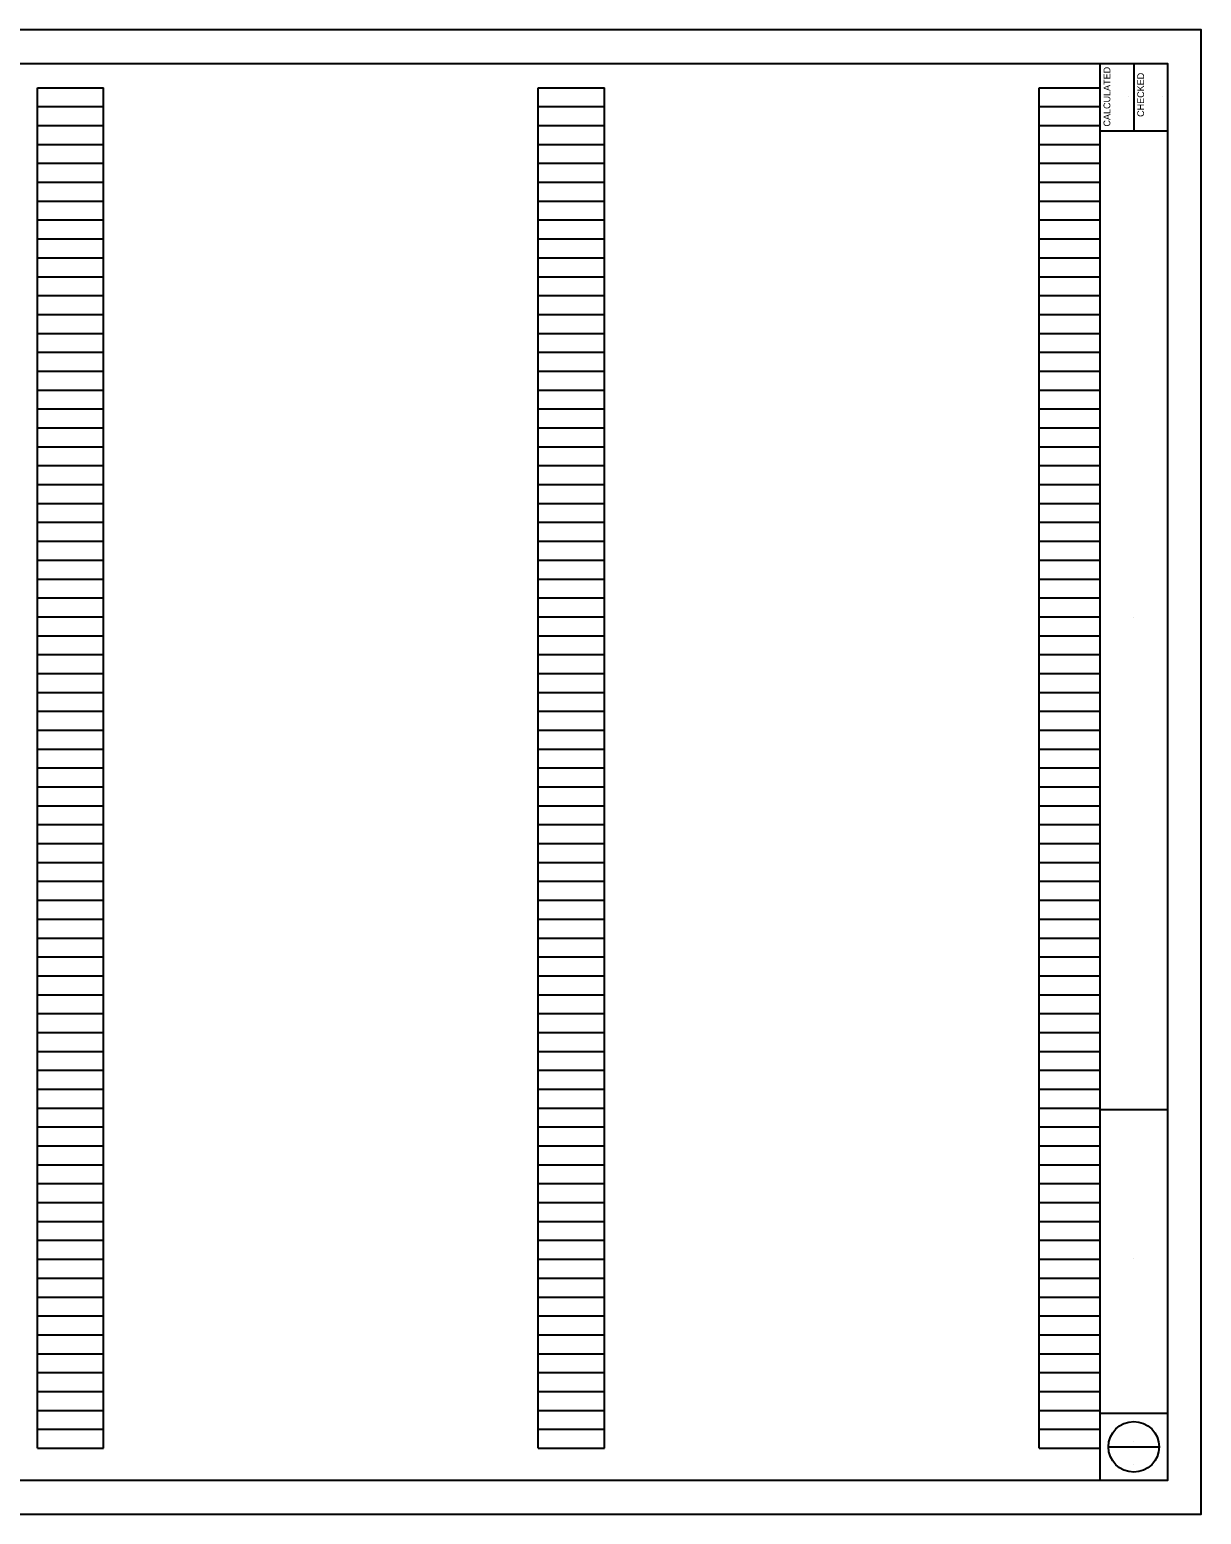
# Model space of a CAD drawing. Extents: x 0 to 34, y 0 to 22.
# Drawn here: x 16.65 to 34, y 0 to 22 of the extents above; entities that cross this region are included whole.
import ezdxf

# ---------------------------------------------------------------- set-up
doc = ezdxf.new("R2010")
doc.units = 0
for name, color, linetype in [('SH_Border', 7, 'Continuous'), ('SH_Cut_Line', 7, 'Continuous'), ('SH_Data', 7, 'Continuous')]:
    doc.layers.add(name, color=color, linetype=linetype)

msp = doc.modelspace()

# ---------------------------------------------------------------- linework, layer by layer
at = {"layer": 'SH_Border'}
for p, q in [((32.5, 0.5), (32.5, 21.5)), ((33, 21.5), (33, 20.5)), ((32.5, 20.5), (33.5, 20.5)), ((32.5, 6), (33.5, 6)), ((32.5, 1.5), (33.5, 1.5))]:
    msp.add_line(p, q, dxfattribs=at)
msp.add_lwpolyline([(2, 21.5), (33.5, 21.5), (33.5, 0.5), (2, 0.5)], close=True, dxfattribs=at)
at = {"layer": 'SH_Cut_Line'}
msp.add_lwpolyline([(0, 0), (34, 0), (34, 22), (0, 22)], close=True, dxfattribs=at)
at = {"layer": 'SH_Data'}
for p, q in [((16.76, 0.98), (16.76, 21.14)), ((16.76, 21.14), (17.74, 21.14)), ((17.74, 0.98), (17.74, 21.14)), ((24.18, 0.98), (24.18, 21.14)), ((24.18, 21.14), (25.16, 21.14)), ((25.16, 0.98), (25.16, 21.14)), ((31.6, 0.98), (31.6, 21.14)), ((31.6, 21.14), (32.5, 21.14)), ((32.5, 0.98), (32.5, 21.14)), ((32.92, 21.004), (32.92, 21.004)), ((33.42, 21.004), (33.42, 21.004)), ((16.76, 20.86), (17.74, 20.86)), ((24.18, 20.86), (25.16, 20.86)), ((31.6, 20.86), (32.5, 20.86)), ((16.76, 20.58), (17.74, 20.58)), ((24.18, 20.58), (25.16, 20.58)), ((31.6, 20.58), (32.5, 20.58)), ((16.76, 20.3), (17.74, 20.3)), ((24.18, 20.3), (25.16, 20.3)), ((31.6, 20.3), (32.5, 20.3)), ((16.76, 20.02), (17.74, 20.02)), ((24.18, 20.02), (25.16, 20.02)), ((31.6, 20.02), (32.5, 20.02)), ((16.76, 19.74), (17.74, 19.74)), ((24.18, 19.74), (25.16, 19.74)), ((31.6, 19.74), (32.5, 19.74)), ((16.76, 19.46), (17.74, 19.46)), ((24.18, 19.46), (25.16, 19.46)), ((31.6, 19.46), (32.5, 19.46)), ((16.76, 19.18), (17.74, 19.18)), ((24.18, 19.18), (25.16, 19.18)), ((31.6, 19.18), (32.5, 19.18)), ((16.76, 18.9), (17.74, 18.9)), ((24.18, 18.9), (25.16, 18.9)), ((31.6, 18.9), (32.5, 18.9)), ((16.76, 18.62), (17.74, 18.62)), ((24.18, 18.62), (25.16, 18.62)), ((31.6, 18.62), (32.5, 18.62)), ((16.76, 18.34), (17.74, 18.34)), ((24.18, 18.34), (25.16, 18.34)), ((31.6, 18.34), (32.5, 18.34)), ((16.76, 18.06), (17.74, 18.06)), ((24.18, 18.06), (25.16, 18.06)), ((31.6, 18.06), (32.5, 18.06)), ((16.76, 17.78), (17.74, 17.78)), ((24.18, 17.78), (25.16, 17.78)), ((31.6, 17.78), (32.5, 17.78)), ((16.76, 17.5), (17.74, 17.5)), ((24.18, 17.5), (25.16, 17.5)), ((31.6, 17.5), (32.5, 17.5)), ((16.76, 17.22), (17.74, 17.22)), ((24.18, 17.22), (25.16, 17.22)), ((31.6, 17.22), (32.5, 17.22)), ((16.76, 16.94), (17.74, 16.94)), ((24.18, 16.94), (25.16, 16.94)), ((31.6, 16.94), (32.5, 16.94)), ((16.76, 16.66), (17.74, 16.66)), ((24.18, 16.66), (25.16, 16.66)), ((31.6, 16.66), (32.5, 16.66)), ((16.76, 16.38), (17.74, 16.38)), ((24.18, 16.38), (25.16, 16.38)), ((31.6, 16.38), (32.5, 16.38)), ((16.76, 16.1), (17.74, 16.1)), ((24.18, 16.1), (25.16, 16.1)), ((31.6, 16.1), (32.5, 16.1)), ((16.76, 15.82), (17.74, 15.82)), ((24.18, 15.82), (25.16, 15.82)), ((31.6, 15.82), (32.5, 15.82)), ((16.76, 15.54), (17.74, 15.54)), ((24.18, 15.54), (25.16, 15.54)), ((31.6, 15.54), (32.5, 15.54)), ((16.76, 15.26), (17.74, 15.26)), ((24.18, 15.26), (25.16, 15.26)), ((31.6, 15.26), (32.5, 15.26)), ((16.76, 14.98), (17.74, 14.98)), ((24.18, 14.98), (25.16, 14.98)), ((31.6, 14.98), (32.5, 14.98)), ((16.76, 14.7), (17.74, 14.7)), ((24.18, 14.7), (25.16, 14.7)), ((31.6, 14.7), (32.5, 14.7)), ((16.76, 14.42), (17.74, 14.42)), ((24.18, 14.42), (25.16, 14.42)), ((31.6, 14.42), (32.5, 14.42)), ((16.76, 14.14), (17.74, 14.14)), ((24.18, 14.14), (25.16, 14.14)), ((31.6, 14.14), (32.5, 14.14)), ((16.76, 13.86), (17.74, 13.86)), ((24.18, 13.86), (25.16, 13.86)), ((31.6, 13.86), (32.5, 13.86)), ((16.76, 13.58), (17.74, 13.58)), ((24.18, 13.58), (25.16, 13.58)), ((31.6, 13.58), (32.5, 13.58)), ((16.76, 13.3), (17.74, 13.3)), ((24.18, 13.3), (25.16, 13.3)), ((31.6, 13.3), (32.5, 13.3)), ((33, 13.292), (33, 13.292)), ((16.76, 13.02), (17.74, 13.02)), ((24.18, 13.02), (25.16, 13.02)), ((31.6, 13.02), (32.5, 13.02)), ((16.76, 12.74), (17.74, 12.74)), ((24.18, 12.74), (25.16, 12.74)), ((31.6, 12.74), (32.5, 12.74)), ((16.76, 12.46), (17.74, 12.46)), ((24.18, 12.46), (25.16, 12.46)), ((31.6, 12.46), (32.5, 12.46)), ((16.76, 12.18), (17.74, 12.18)), ((24.18, 12.18), (25.16, 12.18)), ((31.6, 12.18), (32.5, 12.18)), ((16.76, 11.9), (17.74, 11.9)), ((24.18, 11.9), (25.16, 11.9)), ((31.6, 11.9), (32.5, 11.9)), ((16.76, 11.62), (17.74, 11.62)), ((24.18, 11.62), (25.16, 11.62)), ((31.6, 11.62), (32.5, 11.62)), ((16.76, 11.34), (17.74, 11.34)), ((24.18, 11.34), (25.16, 11.34)), ((31.6, 11.34), (32.5, 11.34)), ((16.76, 11.06), (17.74, 11.06)), ((24.18, 11.06), (25.16, 11.06)), ((31.6, 11.06), (32.5, 11.06)), ((16.76, 10.78), (17.74, 10.78)), ((24.18, 10.78), (25.16, 10.78)), ((31.6, 10.78), (32.5, 10.78)), ((16.76, 10.5), (17.74, 10.5)), ((24.18, 10.5), (25.16, 10.5)), ((31.6, 10.5), (32.5, 10.5)), ((16.76, 10.22), (17.74, 10.22)), ((24.18, 10.22), (25.16, 10.22)), ((31.6, 10.22), (32.5, 10.22)), ((16.76, 9.94), (17.74, 9.94)), ((24.18, 9.94), (25.16, 9.94)), ((31.6, 9.94), (32.5, 9.94)), ((16.76, 9.66), (17.74, 9.66)), ((24.18, 9.66), (25.16, 9.66)), ((31.6, 9.66), (32.5, 9.66)), ((16.76, 9.38), (17.74, 9.38)), ((24.18, 9.38), (25.16, 9.38)), ((31.6, 9.38), (32.5, 9.38)), ((16.76, 9.1), (17.74, 9.1)), ((24.18, 9.1), (25.16, 9.1)), ((31.6, 9.1), (32.5, 9.1)), ((16.76, 8.82), (17.74, 8.82)), ((24.18, 8.82), (25.16, 8.82)), ((31.6, 8.82), (32.5, 8.82)), ((16.76, 8.54), (17.74, 8.54)), ((24.18, 8.54), (25.16, 8.54)), ((31.6, 8.54), (32.5, 8.54)), ((16.76, 8.26), (17.74, 8.26)), ((24.18, 8.26), (25.16, 8.26)), ((31.6, 8.26), (32.5, 8.26)), ((16.76, 7.98), (17.74, 7.98)), ((24.18, 7.98), (25.16, 7.98)), ((31.6, 7.98), (32.5, 7.98)), ((16.76, 7.7), (17.74, 7.7)), ((24.18, 7.7), (25.16, 7.7)), ((31.6, 7.7), (32.5, 7.7)), ((16.76, 7.42), (17.74, 7.42)), ((24.18, 7.42), (25.16, 7.42)), ((31.6, 7.42), (32.5, 7.42)), ((16.76, 7.14), (17.74, 7.14)), ((24.18, 7.14), (25.16, 7.14)), ((31.6, 7.14), (32.5, 7.14)), ((16.76, 6.86), (17.74, 6.86)), ((24.18, 6.86), (25.16, 6.86)), ((31.6, 6.86), (32.5, 6.86)), ((16.76, 6.58), (17.74, 6.58)), ((24.18, 6.58), (25.16, 6.58)), ((31.6, 6.58), (32.5, 6.58)), ((16.76, 6.3), (17.74, 6.3)), ((24.18, 6.3), (25.16, 6.3)), ((31.6, 6.3), (32.5, 6.3)), ((16.76, 6.02), (17.74, 6.02)), ((24.18, 6.02), (25.16, 6.02)), ((31.6, 6.02), (32.5, 6.02)), ((16.76, 5.74), (17.74, 5.74)), ((24.18, 5.74), (25.16, 5.74)), ((31.6, 5.74), (32.5, 5.74)), ((16.76, 5.46), (17.74, 5.46)), ((24.18, 5.46), (25.16, 5.46)), ((31.6, 5.46), (32.5, 5.46)), ((16.76, 5.18), (17.74, 5.18)), ((24.18, 5.18), (25.16, 5.18)), ((31.6, 5.18), (32.5, 5.18)), ((16.76, 4.9), (17.74, 4.9)), ((24.18, 4.9), (25.16, 4.9)), ((31.6, 4.9), (32.5, 4.9)), ((16.76, 4.62), (17.74, 4.62)), ((24.18, 4.62), (25.16, 4.62)), ((31.6, 4.62), (32.5, 4.62)), ((16.76, 4.34), (17.74, 4.34)), ((24.18, 4.34), (25.16, 4.34)), ((31.6, 4.34), (32.5, 4.34)), ((16.76, 4.06), (17.74, 4.06)), ((24.18, 4.06), (25.16, 4.06)), ((31.6, 4.06), (32.5, 4.06)), ((16.76, 3.78), (17.74, 3.78)), ((24.18, 3.78), (25.16, 3.78)), ((31.6, 3.78), (32.5, 3.78)), ((33, 3.792), (33, 3.792)), ((16.76, 3.5), (17.74, 3.5)), ((24.18, 3.5), (25.16, 3.5)), ((31.6, 3.5), (32.5, 3.5)), ((16.76, 3.22), (17.74, 3.22)), ((24.18, 3.22), (25.16, 3.22)), ((31.6, 3.22), (32.5, 3.22)), ((16.76, 2.94), (17.74, 2.94)), ((24.18, 2.94), (25.16, 2.94)), ((31.6, 2.94), (32.5, 2.94)), ((16.76, 2.66), (17.74, 2.66)), ((24.18, 2.66), (25.16, 2.66)), ((31.6, 2.66), (32.5, 2.66)), ((16.76, 2.38), (17.74, 2.38)), ((24.18, 2.38), (25.16, 2.38)), ((31.6, 2.38), (32.5, 2.38)), ((16.76, 2.1), (17.74, 2.1)), ((24.18, 2.1), (25.16, 2.1)), ((31.6, 2.1), (32.5, 2.1)), ((16.76, 1.82), (17.74, 1.82)), ((24.18, 1.82), (25.16, 1.82)), ((31.6, 1.82), (32.5, 1.82)), ((16.76, 1.54), (17.74, 1.54)), ((24.18, 1.54), (25.16, 1.54)), ((31.6, 1.54), (32.5, 1.54)), ((16.76, 1.26), (17.74, 1.26)), ((24.18, 1.26), (25.16, 1.26)), ((31.6, 1.26), (32.5, 1.26)), ((16.76, 0.98), (17.74, 0.98)), ((24.18, 0.98), (25.16, 0.98)), ((31.6, 0.98), (32.5, 0.98)), ((32.625, 1), (33.375, 1)), ((33, 1.085), (33, 1.085)), ((33, 0.745), (33, 0.745))]:
    msp.add_line(p, q, dxfattribs=at)
msp.add_circle((33, 1), 0.375, dxfattribs=at)

# ---------------------------------------------------------------- texts
for s, p in [('CALCULATED', (32.652, 20.565)), ('CHECKED', (33.152, 20.708))]:
    msp.add_text(s, height=0.1, rotation=90, dxfattribs=at).set_placement(p)

doc.saveas('drawing.dxf')
